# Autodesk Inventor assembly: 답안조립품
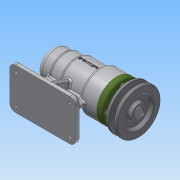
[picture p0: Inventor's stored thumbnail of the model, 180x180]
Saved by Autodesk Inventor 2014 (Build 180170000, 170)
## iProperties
Created: 2016-06
Part Number: 답안조립품
Document SubType Name: Assembly
Designer: 406-8
Author: 406-8
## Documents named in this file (12)
- C:\Users\406-8\Desktop\460607V1019\답안조립품.iam
- C:\Users\406-8\Desktop\460607V1019\1-본체.ipt
- C:\Users\406-8\Desktop\460607V1019\베어링 51202.ipt
- C:\Users\406-8\Desktop\460607V1019\볼트 M4 x 12.ipt
- C:\Users\406-8\Desktop\460607V1019\어댑터슬리브.ipt
- C:\Users\406-8\Desktop\460607V1019\축.ipt
- C:\Users\406-8\Desktop\460607V1019\베어링 6004.ipt
- C:\Users\406-8\Desktop\460607V1019\오일 실.ipt
- C:\Users\406-8\Desktop\460607V1019\커버.ipt
- C:\Users\406-8\Desktop\460607V1019\V벨트풀리.ipt
- C:\Users\406-8\Desktop\460607V1019\키 5 x 5 x 16.ipt
- C:\Users\406-8\Desktop\460607V1019\멈춤나사 M3x8.ipt
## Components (7 placed, 3 different names)
1. 1-본체:1
2. ISO 4762 M4 x 12:1
3. V벨트풀리:1
4. ISO 4762 M4 x 12:2
5. ISO 4762 M4 x 12:3
6. ISO 4762 M4 x 12:4
7. ISO 4762 M4 x 12:5
